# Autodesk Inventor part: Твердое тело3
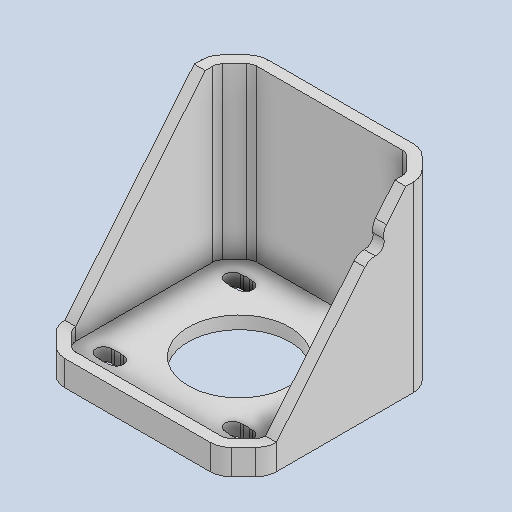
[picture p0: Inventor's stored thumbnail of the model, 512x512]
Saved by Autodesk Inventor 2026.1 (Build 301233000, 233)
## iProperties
Created: 2026-01
Part Number: Твердое тело3
Material: Типовые
Document SubType Name: Modeling
Designer: Yury Melnikov
Density: 1 g/cm^3
Appearance: По умолчанию
Author: Yury Melnikov
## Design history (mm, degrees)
derived "Nema17H44.ipt"
feature "Твердое тело3::Nema17H44.ipt" dims "d0" = 10
tag "Элемент создания тегов1"
node "Твердое тело3"
